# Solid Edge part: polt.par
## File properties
Author: Türk
Template: Iso Part.par
Last saved by: Türk
Revision: 2
Application: Solid Edge
Accuracy: 0,990
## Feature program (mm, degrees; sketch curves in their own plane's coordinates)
thread "unnamed Thread 1"
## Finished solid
Body 1: solid body, 15 faces, 25 edges, 12 vertices.
  Faces by surface: plane 10, cylinder 3, cone 2
  Edges by curve: line 18, circle 7
Bounding box of the edges (mm): 20.000 x 65.000 x 20.000, from (-10, -10, -10) to (10, 55, 10).
Cylindrical faces by radius (mm): R7.5 x2, R10 x1
Conical faces (half-angle, radius in mm at the cone's reference point): 45 deg R9.5 x1, 45 deg R10 x1
Planar faces by outward normal: +x 1, +y 2, -x 1, -y 2, oblique 4
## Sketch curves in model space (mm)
circle centre (0, -10, 0) radius 8.6603
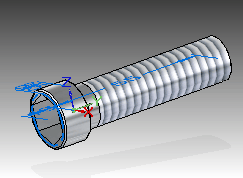
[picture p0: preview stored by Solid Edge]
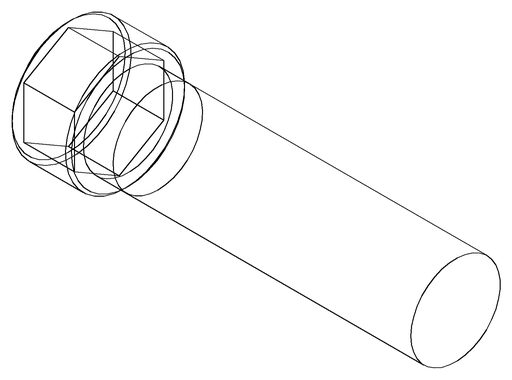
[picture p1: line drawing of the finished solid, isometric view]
